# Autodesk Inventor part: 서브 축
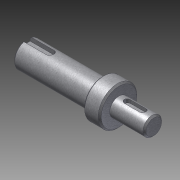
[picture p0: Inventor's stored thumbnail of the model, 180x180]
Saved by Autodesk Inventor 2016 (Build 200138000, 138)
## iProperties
Created: 2014-10
Part Number: 서브 축
Document SubType Name: Modeling
Designer: KYOUNG IL JANG
Density: 1 g/cm^3
Mass: 19.9624 g
Surface Area: 57.7178 cm^2
Volume: 19.9624 cm^3
Material: 강철, 연강
Appearance: 금속-강(스테인리스, 브러시됨)
Author: SeoGD™ [www.esajin.kr]
Revision Number: 1
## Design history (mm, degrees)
sketch "스케치1"
  geometry: L1 (-16.331, 0)-(-98.831, 0); L2 (-16.331, 0)-(-16.331, -6); L3 (-16.331, -6)-(-38.831, -6); L4 (-38.831, -12.5)-(-46.5, -12.5); L5 (-46.5, -8.5)-(-98.831, -8.5); L6 (-98.831, -8.5)-(-98.831, 0); L7 (-46.5, -8.5)-(-46.5, -12.5); L8 (-38.831, -6)-(-38.831, -12.5); L9 (-46.5, 12.249)-(-46.5, -12.249) reference; L10 (-38.831, -17)-(-38.831, 17) reference; 2 further points
  constraints: 17 end point, 4 perpendicular, 2 collinear, 2 parallel, 1 horizontal, 1 midpoint, 1 point on line
  dimensions: "d1" = 12 diameter of L3 L1; "d2" = 25 diameter of L4 L1; "d3" = 17 diameter of L5 L1; "d18" = 22.5 distance of L2.end L3.end; "d20" = 60 distance between parallel lines of L6 L8; "d21" = 7.66872 distance of L4.start L4.end (derived)
revolve "회전1" sketch "스케치1" stored, may be unused: angle "d5" = 90 deg
chamfer "모따기1" distance "d6" = 1; stored, may be unused: second distance "d7" = 2, angle "d8" = 45 deg
node "작업 평면1"
sketch "스케치2"
  geometry: L1 (11.25, 5)-(11.25, -5) reference; L2 (-5.75, -2)-(4.25, -2); L3 (4.25, 2)-(-5.75, 2); A1 r 2 centre (4.25, 0) between (4.25, -2) and (4.25, 2); A2 r 2 centre (-5.75, 0) between (-5.75, 2) and (-5.75, -2); 2 further points
  constraints: 4 end point, 4 point on circle, 4 tangent, 2 centre point, 1 horizontal alignment, 1 midpoint, 1 parallel, 1 perpendicular
  dimensions: "d9" = 4 distance between parallel lines of L2 L3; "d10" = 14 dimension on A1 A2; "d11" = 5 distance edge to line of A1 L1
extrude "돌출1" cut sketch "스케치2" distance "d12" = 2.5; taper "d13" = 0 deg
node "작업 평면2"
sketch "스케치3"
  geometry: L1 (-26.166, -7.5)-(-26.166, 7.5) reference; L2 (-26.166, 2.5)-(-10.666, 2.5); L3 (-10.666, -2.5)-(-26.166, -2.5); A1 r 2.5 centre (-10.666, 0) between (-10.666, -2.5) and (-10.666, 2.5); 2 further points
  constraints: 4 end point, 2 perpendicular, 2 point on circle, 2 point on line, 2 tangent, 1 centre point, 1 horizontal alignment, 1 midpoint
  dimensions: "d14" = 5 distance between parallel lines of L3 L2; "d15" = 18 dimension on A1 L1
extrude "돌출2" cut sketch "스케치3" distance "d16" = 3; taper "d17" = 0 deg
sketch "스케치4"
  geometry: C1 r 12.5 at (0, 0) reference; 1 further point
extrude "돌출3" join sketch "스케치4" distance "d22" = 3; taper "d23" = 0 deg
chamfer "모따기2" distance "d24" = 1; stored, may be unused: second distance "d25" = 2, angle "d26" = 45 deg
node "솔리드1"
node "참조4"
node "참조5"
